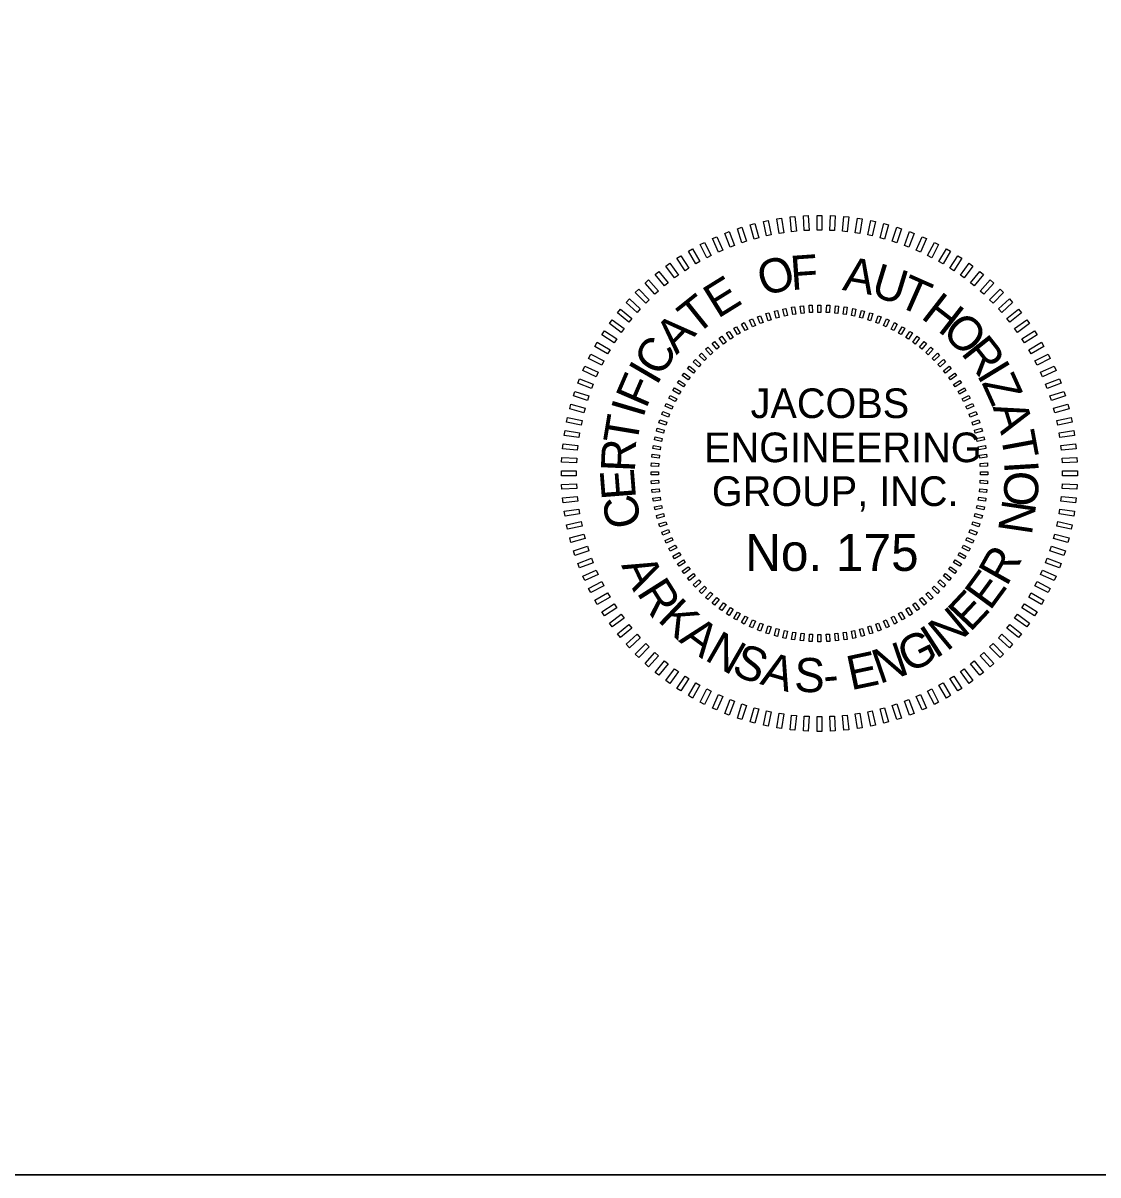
# Model space of a CAD drawing. Extents: x -23882 to 71394, y -5956005 to 2097152.
# Drawn here: x 50517 to 61216, y 1313330 to 1324793 of the extents above; entities that cross this region are included whole.
import ezdxf

# ---------------------------------------------------------------- set-up
doc = ezdxf.new("R2010")
doc.units = 0
doc.layers.add('Certificate of Authorization', color=7, linetype='Continuous')
doc.layers.add('Level 62', color=7, linetype='Continuous')

msp = doc.modelspace()

# ---------------------------------------------------------------- linework, layer by layer
at = {"layer": 'Certificate of Authorization'}
for points in [[(58152, 1322863), (58199, 1322868), (58214, 1322721), (58167, 1322716)], [(58286, 1322874), (58333, 1322877), (58341, 1322730), (58293, 1322727)], [(58420, 1322879), (58467, 1322879), (58467, 1322732), (58420, 1322732)], [(58554, 1322877), (58602, 1322874), (58594, 1322727), (58547, 1322730)], [(58688, 1322868), (58736, 1322863), (58720, 1322716), (58673, 1322721)], [(57628, 1322746), (57673, 1322761), (57718, 1322621), (57673, 1322606)], [(57756, 1322786), (57802, 1322798), (57840, 1322655), (57794, 1322643)], [(57887, 1322818), (57933, 1322828), (57964, 1322684), (57917, 1322674)], [(58019, 1322844), (58065, 1322851), (58088, 1322706), (58042, 1322698)], [(58822, 1322851), (58869, 1322844), (58846, 1322698), (58799, 1322706)], [(58954, 1322828), (59001, 1322818), (58970, 1322674), (58924, 1322684)], [(59085, 1322798), (59131, 1322786), (59093, 1322643), (59047, 1322655)], [(59214, 1322761), (59260, 1322746), (59214, 1322606), (59169, 1322621)], [(57378, 1322648), (57421, 1322667), (57481, 1322532), (57438, 1322513)], [(57501, 1322700), (57546, 1322717), (57598, 1322580), (57554, 1322563)], [(59341, 1322717), (59386, 1322700), (59333, 1322563), (59289, 1322580)], [(59466, 1322667), (59510, 1322648), (59450, 1322513), (59406, 1322532)], [(57139, 1322523), (57180, 1322547), (57254, 1322419), (57213, 1322396)], [(57257, 1322589), (57299, 1322610), (57366, 1322479), (57324, 1322457)], [(59588, 1322610), (59630, 1322589), (59563, 1322457), (59521, 1322479)], [(59707, 1322547), (59748, 1322523), (59674, 1322396), (59633, 1322419)], [(57025, 1322452), (57065, 1322478), (57145, 1322354), (57106, 1322328)], [(59822, 1322478), (59862, 1322452), (59782, 1322328), (59742, 1322354)], [(56809, 1322292), (56846, 1322322), (56939, 1322207), (56902, 1322178)], [(56915, 1322375), (56954, 1322403), (57040, 1322284), (57002, 1322256)], [(59933, 1322403), (59972, 1322375), (59885, 1322256), (59847, 1322284)], [(60041, 1322322), (60078, 1322292), (59985, 1322178), (59948, 1322207)], [(56708, 1322204), (56743, 1322236), (56842, 1322126), (56807, 1322094)], [(60144, 1322236), (60179, 1322204), (60081, 1322094), (60045, 1322126)], [(56611, 1322110), (56645, 1322144), (56749, 1322040), (56716, 1322006)], [(60242, 1322144), (60276, 1322110), (60172, 1322006), (60138, 1322040)], [(56520, 1322012), (56552, 1322047), (56661, 1321949), (56629, 1321913)], [(58080, 1321947), (58110, 1321954), (58125, 1321882), (58096, 1321876)], [(58167, 1321964), (58196, 1321969), (58208, 1321897), (58178, 1321892)], [(58253, 1321976), (58284, 1321980), (58291, 1321907), (58261, 1321904)], [(58341, 1321984), (58371, 1321986), (58375, 1321913), (58345, 1321911)], [(58428, 1321987), (58459, 1321987), (58459, 1321914), (58428, 1321914)], [(58516, 1321986), (58546, 1321984), (58543, 1321911), (58512, 1321913)], [(58604, 1321980), (58634, 1321976), (58626, 1321904), (58596, 1321907)], [(58691, 1321969), (58721, 1321964), (58709, 1321892), (58679, 1321897)], [(58777, 1321954), (58807, 1321947), (58792, 1321876), (58762, 1321882)], [(60336, 1322047), (60367, 1322012), (60258, 1321913), (60226, 1321949)], [(56353, 1321802), (56380, 1321840), (56500, 1321753), (56472, 1321715)], [(56433, 1321909), (56463, 1321946), (56578, 1321853), (56548, 1321816)], [(57748, 1321836), (57776, 1321849), (57806, 1321782), (57778, 1321769)], [(57829, 1321871), (57857, 1321881), (57884, 1321813), (57855, 1321802)], [(57911, 1321901), (57940, 1321910), (57963, 1321840), (57934, 1321831)], [(57995, 1321926), (58025, 1321934), (58044, 1321863), (58014, 1321856)], [(58863, 1321934), (58892, 1321926), (58873, 1321856), (58844, 1321863)], [(58947, 1321910), (58976, 1321901), (58953, 1321831), (58924, 1321840)], [(59030, 1321881), (59058, 1321871), (59032, 1321802), (59004, 1321813)], [(59111, 1321849), (59139, 1321836), (59109, 1321769), (59081, 1321782)], [(60424, 1321946), (60454, 1321909), (60339, 1321816), (60309, 1321853)], [(60507, 1321840), (60535, 1321802), (60415, 1321715), (60387, 1321753)], [(56277, 1321690), (56303, 1321730), (56427, 1321650), (56401, 1321610)], [(57518, 1321709), (57544, 1321725), (57584, 1321664), (57558, 1321647)], [(57593, 1321755), (57619, 1321770), (57656, 1321707), (57629, 1321692)], [(57669, 1321798), (57696, 1321812), (57730, 1321746), (57703, 1321733)], [(59191, 1321812), (59218, 1321798), (59185, 1321733), (59158, 1321746)], [(59268, 1321770), (59294, 1321755), (59258, 1321692), (59232, 1321707)], [(59343, 1321725), (59369, 1321709), (59329, 1321647), (59304, 1321664)], [(60584, 1321730), (60610, 1321690), (60486, 1321610), (60460, 1321650)], [(56208, 1321575), (56232, 1321616), (56360, 1321542), (56336, 1321501)], [(57377, 1321604), (57401, 1321623), (57447, 1321567), (57423, 1321547)], [(57447, 1321658), (57471, 1321676), (57514, 1321617), (57489, 1321599)], [(59416, 1321676), (59441, 1321658), (59398, 1321599), (59373, 1321617)], [(59486, 1321623), (59510, 1321604), (59464, 1321547), (59440, 1321567)], [(60655, 1321616), (60679, 1321575), (60551, 1321501), (60528, 1321542)], [(56145, 1321456), (56167, 1321498), (56298, 1321432), (56277, 1321389)], [(57248, 1321486), (57270, 1321507), (57321, 1321456), (57300, 1321434)], [(57311, 1321547), (57334, 1321567), (57383, 1321513), (57360, 1321492)], [(59553, 1321567), (59576, 1321547), (59527, 1321492), (59504, 1321513)], [(59618, 1321507), (59639, 1321486), (59587, 1321434), (59566, 1321456)], [(60720, 1321498), (60742, 1321456), (60611, 1321389), (60589, 1321432)], [(56089, 1321334), (56108, 1321378), (56242, 1321318), (56223, 1321274)], [(57132, 1321354), (57151, 1321378), (57208, 1321332), (57189, 1321308)], [(57188, 1321422), (57209, 1321444), (57263, 1321395), (57243, 1321373)], [(59679, 1321444), (59699, 1321422), (59644, 1321373), (59624, 1321395)], [(59736, 1321378), (59755, 1321354), (59698, 1321308), (59679, 1321332)], [(60779, 1321378), (60799, 1321334), (60664, 1321274), (60645, 1321318)], [(57079, 1321284), (57097, 1321309), (57156, 1321266), (57138, 1321241)], [(59790, 1321309), (59808, 1321284), (59749, 1321241), (59731, 1321266)], [(56038, 1321210), (56055, 1321254), (56193, 1321201), (56176, 1321157)], [(56985, 1321136), (57000, 1321163), (57063, 1321126), (57048, 1321100)], [(57030, 1321212), (57047, 1321237), (57108, 1321197), (57091, 1321172)], [(59840, 1321237), (59857, 1321212), (59796, 1321172), (59779, 1321197)], [(59887, 1321163), (59902, 1321136), (59839, 1321100), (59824, 1321126)], [(60832, 1321254), (60849, 1321210), (60711, 1321157), (60694, 1321201)], [(55995, 1321083), (56009, 1321128), (56149, 1321082), (56135, 1321037)], [(56944, 1321059), (56958, 1321086), (57023, 1321053), (57009, 1321026)], [(59930, 1321086), (59943, 1321059), (59878, 1321026), (59864, 1321053)], [(60878, 1321128), (60893, 1321083), (60753, 1321037), (60738, 1321082)], [(55958, 1320953), (55970, 1320999), (56112, 1320961), (56100, 1320915)], [(56874, 1320898), (56885, 1320926), (56953, 1320900), (56942, 1320872)], [(56907, 1320979), (56919, 1321007), (56986, 1320977), (56974, 1320950)], [(59968, 1321007), (59980, 1320979), (59914, 1320950), (59901, 1320977)], [(60002, 1320926), (60013, 1320898), (59945, 1320872), (59934, 1320900)], [(60917, 1320999), (60930, 1320953), (60787, 1320915), (60775, 1320961)], [(55927, 1320822), (55937, 1320869), (56081, 1320838), (56071, 1320792)], [(56845, 1320815), (56855, 1320844), (56924, 1320821), (56915, 1320793)], [(60032, 1320844), (60042, 1320815), (59972, 1320793), (59963, 1320821)], [(60950, 1320869), (60960, 1320822), (60816, 1320792), (60806, 1320838)], [(55904, 1320690), (55912, 1320737), (56057, 1320714), (56050, 1320667)], [(56821, 1320731), (56829, 1320760), (56900, 1320741), (56892, 1320712)], [(60058, 1320760), (60066, 1320731), (59995, 1320712), (59987, 1320741)], [(60976, 1320737), (60983, 1320690), (60838, 1320667), (60830, 1320714)], [(55888, 1320557), (55893, 1320604), (56039, 1320588), (56034, 1320541)], [(56786, 1320559), (56791, 1320589), (56863, 1320577), (56859, 1320547)], [(56802, 1320645), (56808, 1320675), (56879, 1320660), (56873, 1320630)], [(60079, 1320675), (60086, 1320645), (60014, 1320630), (60008, 1320660)], [(60096, 1320589), (60101, 1320559), (60029, 1320547), (60024, 1320577)], [(60994, 1320604), (60999, 1320557), (60853, 1320541), (60848, 1320588)], [(55878, 1320422), (55881, 1320470), (56028, 1320462), (56026, 1320415)], [(56776, 1320472), (56779, 1320502), (56852, 1320494), (56848, 1320464)], [(60108, 1320502), (60111, 1320472), (60039, 1320464), (60036, 1320494)], [(61006, 1320470), (61009, 1320422), (60862, 1320415), (60859, 1320462)], [(56770, 1320384), (56771, 1320415), (56844, 1320411), (56843, 1320380)], [(60116, 1320415), (60118, 1320384), (60045, 1320380), (60043, 1320411)], [(55876, 1320288), (55876, 1320336), (56024, 1320336), (56024, 1320288)], [(56768, 1320297), (56768, 1320327), (56841, 1320327), (56841, 1320297)], [(56771, 1320209), (56770, 1320239), (56843, 1320243), (56844, 1320213)], [(60118, 1320239), (60116, 1320209), (60043, 1320213), (60045, 1320243)], [(60119, 1320327), (60119, 1320297), (60046, 1320297), (60046, 1320327)], [(61011, 1320336), (61011, 1320288), (60864, 1320288), (60864, 1320336)], [(55881, 1320154), (55878, 1320201), (56026, 1320209), (56028, 1320161)], [(56779, 1320122), (56776, 1320152), (56848, 1320159), (56852, 1320129)], [(60111, 1320152), (60108, 1320122), (60036, 1320129), (60039, 1320159)], [(61009, 1320201), (61006, 1320154), (60859, 1320161), (60862, 1320209)], [(55893, 1320020), (55888, 1320067), (56034, 1320082), (56039, 1320035)], [(56791, 1320035), (56786, 1320065), (56859, 1320076), (56863, 1320046)], [(60101, 1320065), (60096, 1320035), (60024, 1320046), (60029, 1320076)], [(60999, 1320067), (60994, 1320020), (60848, 1320035), (60853, 1320082)], [(55912, 1319887), (55904, 1319934), (56050, 1319957), (56057, 1319910)], [(56808, 1319949), (56802, 1319978), (56873, 1319993), (56879, 1319964)], [(56829, 1319863), (56821, 1319893), (56892, 1319912), (56900, 1319882)], [(60066, 1319893), (60058, 1319863), (59987, 1319882), (59995, 1319912)], [(60086, 1319978), (60079, 1319949), (60008, 1319964), (60014, 1319993)], [(60983, 1319934), (60976, 1319887), (60830, 1319910), (60838, 1319957)], [(55937, 1319755), (55927, 1319801), (56071, 1319832), (56081, 1319785)], [(56855, 1319780), (56845, 1319808), (56915, 1319831), (56924, 1319802)], [(60042, 1319808), (60032, 1319780), (59963, 1319802), (59972, 1319831)], [(60960, 1319801), (60950, 1319755), (60806, 1319785), (60816, 1319832)], [(55970, 1319624), (55958, 1319670), (56100, 1319708), (56112, 1319662)], [(56885, 1319697), (56874, 1319725), (56942, 1319752), (56953, 1319723)], [(56919, 1319616), (56907, 1319644), (56974, 1319674), (56986, 1319646)], [(59980, 1319644), (59968, 1319616), (59901, 1319646), (59914, 1319674)], [(60013, 1319725), (60002, 1319697), (59934, 1319723), (59945, 1319752)], [(60930, 1319670), (60917, 1319624), (60775, 1319662), (60787, 1319708)], [(56009, 1319496), (55995, 1319541), (56135, 1319587), (56149, 1319541)], [(56958, 1319538), (56944, 1319565), (57009, 1319598), (57023, 1319571)], [(59943, 1319565), (59930, 1319538), (59864, 1319571), (59878, 1319598)], [(60893, 1319541), (60878, 1319496), (60738, 1319541), (60753, 1319587)], [(56055, 1319370), (56038, 1319414), (56176, 1319467), (56193, 1319422)], [(57000, 1319461), (56985, 1319487), (57048, 1319524), (57063, 1319497)], [(57047, 1319387), (57030, 1319412), (57091, 1319452), (57108, 1319426)], [(59857, 1319412), (59840, 1319387), (59779, 1319426), (59796, 1319452)], [(59902, 1319487), (59887, 1319461), (59824, 1319497), (59839, 1319524)], [(60849, 1319414), (60832, 1319370), (60694, 1319422), (60711, 1319467)], [(56108, 1319246), (56089, 1319289), (56223, 1319349), (56242, 1319306)], [(57097, 1319315), (57079, 1319339), (57138, 1319382), (57156, 1319358)], [(57151, 1319246), (57132, 1319269), (57189, 1319315), (57208, 1319292)], [(59755, 1319269), (59736, 1319246), (59679, 1319292), (59698, 1319315)], [(59808, 1319339), (59790, 1319315), (59731, 1319358), (59749, 1319382)], [(60799, 1319289), (60779, 1319246), (60645, 1319306), (60664, 1319349)], [(56167, 1319125), (56145, 1319167), (56277, 1319234), (56298, 1319192)], [(57209, 1319179), (57188, 1319202), (57243, 1319251), (57263, 1319228)], [(59699, 1319202), (59679, 1319179), (59624, 1319228), (59644, 1319251)], [(60742, 1319167), (60720, 1319125), (60589, 1319192), (60611, 1319234)], [(56232, 1319008), (56208, 1319049), (56336, 1319122), (56360, 1319081)], [(57270, 1319116), (57248, 1319138), (57300, 1319189), (57321, 1319168)], [(57334, 1319057), (57311, 1319077), (57360, 1319131), (57383, 1319111)], [(59576, 1319077), (59553, 1319057), (59504, 1319111), (59527, 1319131)], [(59639, 1319138), (59618, 1319116), (59566, 1319168), (59587, 1319189)], [(60679, 1319049), (60655, 1319008), (60528, 1319081), (60551, 1319122)], [(56303, 1318894), (56277, 1318933), (56401, 1319014), (56427, 1318974)], [(57401, 1319000), (57377, 1319019), (57423, 1319076), (57447, 1319057)], [(57471, 1318947), (57447, 1318965), (57489, 1319024), (57514, 1319007)], [(57544, 1318898), (57518, 1318915), (57558, 1318976), (57584, 1318960)], [(59369, 1318915), (59343, 1318898), (59304, 1318960), (59329, 1318976)], [(59441, 1318965), (59416, 1318947), (59373, 1319007), (59398, 1319024)], [(59510, 1319019), (59486, 1319000), (59440, 1319057), (59464, 1319076)], [(60610, 1318933), (60584, 1318894), (60460, 1318974), (60486, 1319014)], [(56380, 1318783), (56353, 1318822), (56472, 1318909), (56500, 1318870)], [(57619, 1318853), (57593, 1318868), (57629, 1318932), (57656, 1318917)], [(57696, 1318812), (57669, 1318826), (57703, 1318891), (57730, 1318877)], [(57776, 1318775), (57748, 1318787), (57778, 1318854), (57806, 1318842)], [(59139, 1318787), (59111, 1318775), (59081, 1318842), (59109, 1318854)], [(59218, 1318826), (59191, 1318812), (59158, 1318877), (59185, 1318891)], [(59294, 1318868), (59268, 1318853), (59232, 1318917), (59258, 1318932)], [(60535, 1318822), (60507, 1318783), (60387, 1318870), (60415, 1318909)], [(56463, 1318678), (56433, 1318715), (56548, 1318807), (56578, 1318770)], [(57857, 1318742), (57829, 1318753), (57855, 1318821), (57884, 1318810)], [(57940, 1318714), (57911, 1318723), (57934, 1318793), (57963, 1318783)], [(58025, 1318689), (57995, 1318697), (58014, 1318768), (58044, 1318760)], [(58110, 1318670), (58080, 1318676), (58096, 1318748), (58125, 1318741)], [(58807, 1318676), (58777, 1318670), (58762, 1318741), (58792, 1318748)], [(58892, 1318697), (58863, 1318689), (58844, 1318760), (58873, 1318768)], [(58976, 1318723), (58947, 1318714), (58924, 1318783), (58953, 1318793)], [(59058, 1318753), (59030, 1318742), (59004, 1318810), (59032, 1318821)], [(60454, 1318715), (60424, 1318678), (60309, 1318770), (60339, 1318807)], [(56552, 1318576), (56520, 1318612), (56629, 1318710), (56661, 1318675)], [(58196, 1318655), (58167, 1318659), (58178, 1318732), (58208, 1318727)], [(58284, 1318644), (58253, 1318647), (58261, 1318720), (58291, 1318717)], [(58371, 1318638), (58341, 1318639), (58345, 1318712), (58375, 1318711)], [(58459, 1318636), (58428, 1318636), (58428, 1318709), (58459, 1318709)], [(58546, 1318639), (58516, 1318638), (58512, 1318711), (58543, 1318712)], [(58634, 1318647), (58604, 1318644), (58596, 1318717), (58626, 1318720)], [(58721, 1318659), (58691, 1318655), (58679, 1318727), (58709, 1318732)], [(60367, 1318612), (60336, 1318576), (60226, 1318675), (60258, 1318710)], [(56645, 1318480), (56611, 1318513), (56716, 1318617), (56749, 1318584)], [(56743, 1318388), (56708, 1318420), (56807, 1318529), (56842, 1318497)], [(60179, 1318420), (60144, 1318388), (60045, 1318497), (60081, 1318529)], [(60276, 1318513), (60242, 1318480), (60138, 1318584), (60172, 1318617)], [(56846, 1318302), (56809, 1318331), (56902, 1318446), (56939, 1318416)], [(60078, 1318331), (60041, 1318302), (59948, 1318416), (59985, 1318446)], [(56954, 1318221), (56915, 1318249), (57002, 1318368), (57040, 1318340)], [(57065, 1318146), (57025, 1318172), (57106, 1318295), (57145, 1318269)], [(59862, 1318172), (59822, 1318146), (59742, 1318269), (59782, 1318295)], [(59972, 1318249), (59933, 1318221), (59847, 1318340), (59885, 1318368)], [(57180, 1318076), (57139, 1318100), (57213, 1318228), (57254, 1318204)], [(57299, 1318013), (57257, 1318035), (57324, 1318166), (57366, 1318145)], [(59630, 1318035), (59588, 1318013), (59521, 1318145), (59563, 1318166)], [(59748, 1318100), (59707, 1318076), (59633, 1318204), (59674, 1318228)], [(57421, 1317957), (57378, 1317976), (57438, 1318111), (57481, 1318091)], [(57546, 1317906), (57501, 1317923), (57554, 1318061), (57598, 1318044)], [(59386, 1317923), (59341, 1317906), (59289, 1318044), (59333, 1318061)], [(59510, 1317976), (59466, 1317957), (59406, 1318091), (59450, 1318111)], [(57673, 1317863), (57628, 1317877), (57673, 1318018), (57718, 1318003)], [(57802, 1317826), (57756, 1317838), (57794, 1317980), (57840, 1317968)], [(57933, 1317796), (57887, 1317805), (57917, 1317950), (57964, 1317940)], [(59001, 1317805), (58954, 1317796), (58924, 1317940), (58970, 1317950)], [(59131, 1317838), (59085, 1317826), (59047, 1317968), (59093, 1317980)], [(59260, 1317877), (59214, 1317863), (59169, 1318003), (59214, 1318018)], [(58065, 1317772), (58019, 1317780), (58042, 1317925), (58088, 1317918)], [(58199, 1317756), (58152, 1317761), (58167, 1317907), (58214, 1317903)], [(58333, 1317747), (58286, 1317749), (58293, 1317896), (58341, 1317894)], [(58467, 1317744), (58420, 1317744), (58420, 1317892), (58467, 1317892)], [(58602, 1317749), (58554, 1317747), (58547, 1317894), (58594, 1317896)], [(58736, 1317761), (58688, 1317756), (58673, 1317903), (58720, 1317907)], [(58869, 1317780), (58822, 1317772), (58799, 1317918), (58846, 1317925)]]:
    msp.add_lwpolyline(points, close=True, dxfattribs=at)
at = {"layer": 'Level 62'}
for points in [[(-16145, 1313330), (70490, 1313330), (70490, 1368515), (-16145, 1368515)], [(-15590, 1368515), (71046, 1368515), (71046, 1313330), (-15590, 1313330)]]:
    msp.add_lwpolyline(points, close=True, dxfattribs=at)

# ---------------------------------------------------------------- texts
at = {"layer": 'Certificate of Authorization'}
for s, rotation, p in [('O', 17.9056, (57892, 1322067)), ('F', 3.9823, (58164, 1322135)), ('A', 350.059, (58665, 1322138)), ('U', 343.0974, (58943, 1322082)), ('T', 336.1357, (59202, 1321986)), ('E', 31.8289, (57432, 1321847)), ('T', 38.7906, (57213, 1321677)), ('H', 322.2124, (59443, 1321863)), ('A', 45.7522, (57021, 1321486)), ('O', 315.2507, (59650, 1321708)), ('C', 59.6755, (56873, 1321260)), ('R', 308.2891, (59845, 1321507)), ('I', 59.6755, (56823, 1321177)), ('I', 301.3274, (60003, 1321291)), ('F', 66.6372, (56718, 1320948)), ('Z', 294.3658, (60055, 1321214)), ('I', 73.5988, (56690, 1320855)), ('A', 287.4041, (60166, 1320973)), ('T', 80.5605, (56626, 1320584)), ('T', 280.4425, (60244, 1320704)), ('R', 87.5222, (56607, 1320321)), ('E', 94.4838, (56619, 1320064)), ('I', 273.4808, (60281, 1320429)), ('O', 267.5222, (60290, 1320343)), ('C', 101.4455, (56675, 1319802)), ('N', 261.5635, (60268, 1320064)), ('R', 60.6785, (60308, 1319178)), ('A', 295.3688, (56468, 1319397)), ('E', 53.7169, (60142, 1318937)), ('R', 302.3304, (56619, 1319125)), ('E', 46.7552, (59944, 1318724)), ('K', 316.2537, (56823, 1318850)), ('N', 39.7936, (59712, 1318532)), ('A', 323.2154, (57036, 1318643)), ('N', 330.177, (57290, 1318461)), ('I', 32.8319, (59598, 1318461)), ('N', 18.9086, (59042, 1318214)), ('G', 25.8703, (59329, 1318319)), ('S', 337.1387, (57556, 1318322)), ('A', 344.1003, (57843, 1318217)), ('E', 11.9469, (58757, 1318152)), ('S', 358.0236, (58189, 1318140)), ('-', 4.9853, (58495, 1318130))]:
    msp.add_text(s, height=340, rotation=rotation, dxfattribs=at).set_placement(p)
for s, height, p in [('JACOBS', 295, (57759, 1320862)), ('ENGINEERING', 295.03, (57296, 1320423)), ('GROUP, INC.', 295.03, (57373, 1319987)), ('No. 175', 368.8, (57704, 1319341))]:
    msp.add_text(s, height=height, dxfattribs=at).set_placement(p)

doc.saveas('drawing.dxf')
